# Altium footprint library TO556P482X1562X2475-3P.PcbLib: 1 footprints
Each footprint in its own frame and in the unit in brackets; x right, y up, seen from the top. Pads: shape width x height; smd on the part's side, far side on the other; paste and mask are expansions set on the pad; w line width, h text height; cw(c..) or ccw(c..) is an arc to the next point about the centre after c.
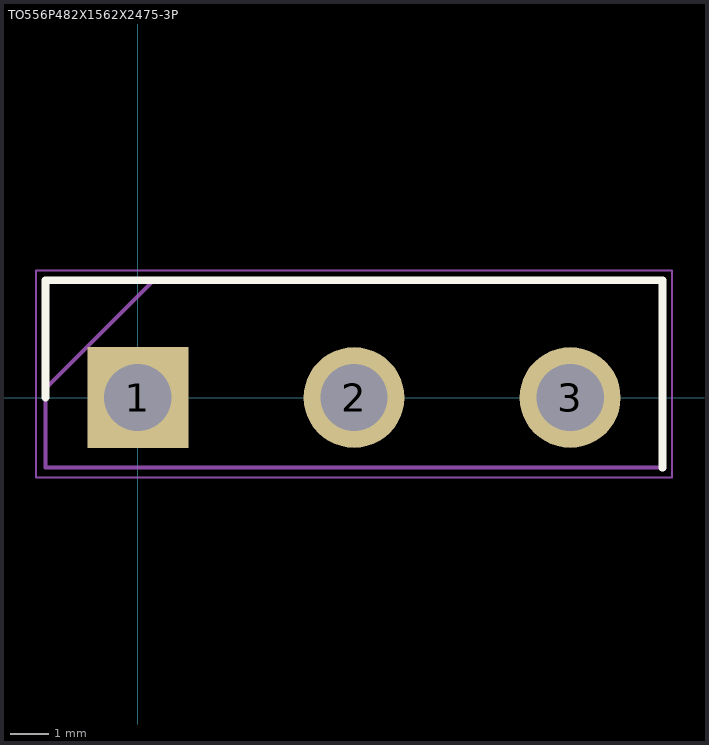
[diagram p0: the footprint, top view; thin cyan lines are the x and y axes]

## TO556P482X1562X2475-3P [mm]
pads (3):
  rect 2.595x2.595 / inner round 2.595 / far side rect 2.595x2.595 hole 1.73: 1(0,0)
  round 2.595 hole 1.73: 2(5.56,0) 3(11.12,0)
Top Overlay:
  lines w0.2: -2.375,0 -2.375,3.015 13.495,3.015 13.495,-1.805
Mechanical 15:
  lines w0.1: -2.375,0.235 0.405,3.015 ; -2.375,-1.805 13.495,-1.805 13.495,3.015 -2.375,3.015 -2.375,-1.805
Mechanical 20:
  lines w0.05: -2.625,-2.055 13.745,-2.055 13.745,3.265 -2.625,3.265 -2.625,-2.055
